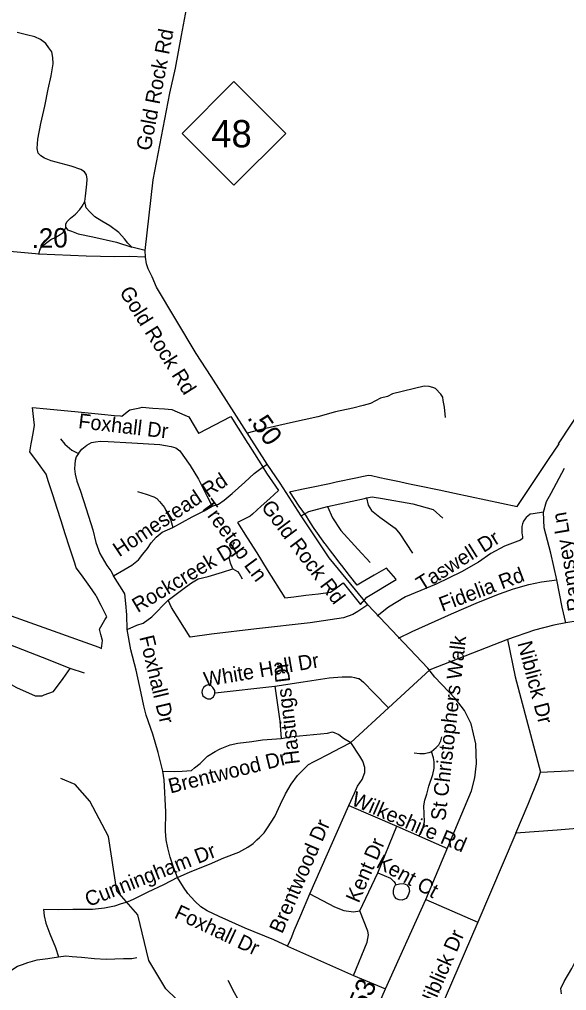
# Model space of a CAD drawing. Extents: x 2220236 to 2384410, y 720751 to 894131.
# Drawn here: x 2350546 to 2354061, y 819071 to 825303 of the extents above; entities that cross this region are included whole.
import ezdxf

# ---------------------------------------------------------------- set-up
doc = ezdxf.new("R2010")
doc.units = 0
doc.layers.add('Default', color=7, linetype='Continuous')

msp = doc.modelspace()

# ---------------------------------------------------------------- linework, layer by layer
at = {"layer": 'Default'}
for p, q in [((2351353.9, 823820.3), (2351267.5, 823841.9)), ((2353681.2, 821325.1), (2353181.5, 821129.2)), ((2350964.3, 821107), (2350872.7, 821138.5)), ((2352916.6, 820884.9), (2353181.5, 821129.2)), ((2351803.3, 820981.7), (2352186.3, 821025.3)), ((2352674.6, 820662.3), (2352916.6, 820884.9)), ((2353892.4, 820473.1), (2354855.4, 820516.7)), ((2352411.4, 819691.4), (2352661.1, 820257.9)), ((2352661.1, 820257.9), (2352969.9, 820125.3)), ((2352848.4, 819825.8), (2352969.9, 820125.3)), ((2352969.9, 820125.3), (2353295.3, 819983.3)), ((2353735.1, 820081.3), (2353490.1, 819510.5)), ((2352733.4, 819583.5), (2352848.4, 819825.8)), ((2353156.4, 819656.6), (2353490.1, 819510.5)), ((2352267.7, 819356), (2352691.2, 819167.9)), ((2352691.2, 819167.9), (2352898.6, 819081.8))]:
    msp.add_line(p, q, dxfattribs=at)
for points in [[(2351355.5, 823776.5), (2351353.9, 823820.3), (2351405, 824274.2), (2351513.6, 824829), (2351549.3, 824991.3), (2351587.4, 825199.7), (2351625.8, 825406.1)], [(2350966.1, 824135.1), (2350971.9, 824170), (2350978.9, 824246.8), (2350982.4, 824278.3), (2350977.1, 824306.2), (2350964.9, 824325.4), (2350940.5, 824341.1), (2350878.6, 824362.1), (2350751.2, 824395.2), (2350707.6, 824412.7), (2350684.9, 824428.4), (2350667.5, 824445.8), (2350660.5, 824475.5), (2350664, 824534.9), (2350683.2, 824636.1), (2350709.3, 824746.1), (2350730.3, 824856.1), (2350749.5, 824941.6), (2350763.4, 825018.5), (2350761.7, 825058.6), (2350754.7, 825095.3), (2350735.5, 825121.5), (2350716.3, 825149.4), (2350681.4, 825173.8), (2350646.5, 825191.3), (2350592.4, 825205.3), (2350533.1, 825219.2)], [(2350844.1, 823968.4), (2350844.1, 823989.3), (2350851.1, 824005), (2350873.8, 824027.7), (2350906.9, 824053.9), (2350934.8, 824083.6), (2350950.5, 824104.6), (2350966.1, 824135.1)], [(2351267.5, 823841.9), (2351242.3, 823868), (2351221.4, 823894.2), (2351184.8, 823936.1), (2351127.2, 823978), (2351074.8, 824007.7), (2351031.2, 824035.6), (2350998.1, 824068.8), (2350975.4, 824094.9), (2350966.1, 824135.1)], [(2350671.4, 823795.5), (2350676.6, 823821.7), (2350681.9, 823834), (2350690.6, 823846.2), (2350722, 823872.4), (2350748.2, 823891.6), (2350781.3, 823905.5), (2350809.2, 823923), (2350826.7, 823935.2), (2350833.6, 823945.7), (2350844.1, 823968.4)], [(2350844.1, 823968.4), (2350856.3, 823952.7), (2350880.8, 823943.9), (2350924.4, 823928.2), (2351018.6, 823909), (2351170.4, 823874.1), (2351267.5, 823841.9)], [(2351355.5, 823776.5), (2351251.8, 823781.3), (2351158.6, 823780.7), (2350975.6, 823783.5), (2350674.4, 823796.4), (2350249.6, 823834.8)], [(2352651.8, 818514.5), (2352898.6, 819081.8), (2353156.4, 819656.6), (2353450.9, 820353.6), (2353471.4, 820436.2), (2353482.4, 820529.3), (2353478.2, 820655.6), (2353448.2, 820783.4), (2353405.1, 820867.6), (2353346.9, 820944.3), (2353214.8, 821083.3), (2353170.1, 821139.6), (2352784.6, 821547.5), (2352535.8, 821847.6), (2352355.3, 822118.1), (2352220.4, 822327), (2352138.6, 822448.7), (2351778.7, 823010.8), (2351681.4, 823158.4), (2351426.1, 823584.2), (2351398.5, 823650.8), (2351373.4, 823701.9), (2351361.8, 823735.5), (2351355.5, 823776.5)], [(2350079.2, 821624.6), (2351057, 821275.5), (2351074, 821267.1), (2351081, 821317.6), (2351070.2, 821356.4), (2351061, 821390.7), (2351096, 821450), (2351107.8, 821470), (2351071.8, 821541.6), (2351042.5, 821599.9), (2351038.2, 821608.3), (2350998.2, 821663.9), (2350944.5, 821738.5), (2350911.5, 821784.3), (2350901.8, 821814.8), (2350869, 821916.4), (2350841.2, 822002.4), (2350814.5, 822085.4), (2350788.8, 822165.6), (2350760.8, 822252.1), (2350734, 822334.9), (2350718, 822384.9), (2350668, 822453.7), (2350614.2, 822528.9), (2350622.8, 822579.4), (2350634.8, 822646), (2350644.2, 822699.1), (2350640, 822735.9), (2350630.8, 822812.1), (2350723, 822803.3), (2350923.5, 822784.2), (2351074.2, 822769.9), (2351156.5, 822762.1), (2351196, 822758.3), (2351204.5, 822757.5), (2351237.8, 822784.2), (2351255, 822798.1), (2351319.8, 822811.1), (2351334.8, 822814.1), (2351404.2, 822809.1), (2351478.8, 822803.8), (2351526.2, 822800.3), (2351608.8, 822763.6), (2351634.2, 822752.1), (2351696.8, 822647.9), (2351698.5, 822648.7), (2351904, 822754.3), (2351950.8, 822680.4), (2352013.5, 822581.4), (2352014.8, 822579.4), (2352082.5, 822475.1), (2352086, 822469.5), (2352133.2, 822391.4), (2352211, 822280.1), (2352155.2, 822229.6), (2352099, 822178.8), (2352043.2, 822128.4), (2352029.5, 822116.1), (2351967.5, 822084.9), (2351948, 822075), (2352009.5, 821977.1), (2352070.5, 821879.9), (2352138.5, 821771.6), (2352251.5, 821591.6), (2352308.2, 821598.5), (2352386.2, 821608.1), (2352468, 821618.1), (2352545, 821627.4), (2352579.8, 821653), (2352582.2, 821655.8), (2352626.8, 821688.4), (2352736.5, 821547.8), (2352777.5, 821594.7), (2352967, 821708.9), (2352964, 821712.6), (2352933.8, 821747.6), (2352903.5, 821782.6), (2352899.8, 821780.3), (2352824.2, 821736.2), (2352748.2, 821691.9), (2352715.2, 821672.7), (2352667, 821734.9), (2352616.5, 821799.5), (2352605, 821814.1), (2352600, 821820.8), (2352579.2, 821847.2), (2352573.5, 821854.8), (2352544.8, 821892.6), (2352512, 821935.8), (2352509, 821939.8), (2352487.5, 821970.3), (2352461.2, 822007.1), (2352440.2, 822036.6), (2352436, 822042.9), (2352404.2, 822090.1), (2352390.2, 822115.1), (2352344.2, 822179.2), (2352283.8, 822271.8), (2352289.2, 822273), (2352369.8, 822290.1), (2352412.5, 822299.2), (2352454, 822308.1), (2352496, 822317.1), (2352538.2, 822326.1), (2352580.2, 822335), (2352622.8, 822344.1), (2352664.2, 822352.9), (2352706.2, 822361.9), (2352755.8, 822372.4), (2352789, 822379.6), (2352808, 822375.6), (2352861.8, 822364.2), (2352902.5, 822355.6), (2352945, 822346.6), (2352986.8, 822337.7), (2353033.2, 822327.8), (2353072.8, 822319.4), (2353115.2, 822310.4), (2353158.2, 822301.4), (2353200.5, 822292.4), (2353242.5, 822283.5), (2353341.2, 822262.6), (2353743.2, 822177.5), (2353944.5, 822478.4), (2353945, 822479.4), (2354012, 822579.4), (2354009.5, 822579.4), (2354356.2, 823104.4)], [(2350079.2, 821624.6), (2351057, 821275.5), (2351074, 821267.1), (2351081, 821317.6), (2351070.2, 821356.4), (2351061, 821390.7), (2351096, 821450), (2351107.8, 821470), (2351071.8, 821541.6), (2351042.5, 821599.9), (2351038.2, 821608.3), (2350998.2, 821663.9), (2350944.5, 821738.5), (2350911.5, 821784.3), (2350901.8, 821814.8), (2350869, 821916.4), (2350841.2, 822002.4), (2350814.5, 822085.4), (2350788.8, 822165.6), (2350760.8, 822252.1), (2350734, 822334.9), (2350718, 822384.9), (2350668, 822453.7), (2350614.2, 822528.9), (2350622.8, 822579.4), (2350634.8, 822646), (2350644.2, 822699.1), (2350640, 822735.9), (2350630.8, 822812.1), (2350723, 822803.3), (2350923.5, 822784.2), (2351074.2, 822769.9), (2351156.5, 822762.1), (2351196, 822758.3), (2351204.5, 822757.5), (2351237.8, 822784.2), (2351255, 822798.1), (2351319.8, 822811.1), (2351334.8, 822814.1), (2351404.2, 822809.1), (2351478.8, 822803.8), (2351526.2, 822800.3), (2351608.8, 822763.6), (2351634.2, 822752.1), (2351696.8, 822647.9), (2351698.5, 822648.7), (2351904, 822754.3), (2351950.8, 822680.4), (2352013.5, 822581.4), (2352014.8, 822579.4), (2352082.5, 822475.1), (2352086, 822469.5), (2352133.2, 822391.4), (2352211, 822280.1), (2352155.2, 822229.6), (2352099, 822178.8), (2352043.2, 822128.4), (2352029.5, 822116.1), (2351967.5, 822084.9), (2351948, 822075), (2352009.5, 821977.1), (2352070.5, 821879.9), (2352138.5, 821771.6), (2352251.5, 821591.6), (2352308.2, 821598.5), (2352386.2, 821608.1), (2352468, 821618.1), (2352545, 821627.4), (2352579.8, 821653), (2352582.2, 821655.8), (2352626.8, 821688.4), (2352736.5, 821547.8), (2352777.5, 821594.7), (2352967, 821708.9), (2352964, 821712.6), (2352933.8, 821747.6), (2352903.5, 821782.6), (2352899.8, 821780.3), (2352824.2, 821736.2), (2352748.2, 821691.9), (2352715.2, 821672.7), (2352667, 821734.9), (2352616.5, 821799.5), (2352605, 821814.1), (2352600, 821820.8), (2352579.2, 821847.2), (2352573.5, 821854.8), (2352544.8, 821892.6), (2352512, 821935.8), (2352509, 821939.8), (2352487.5, 821970.3), (2352461.2, 822007.1), (2352440.2, 822036.6), (2352436, 822042.9), (2352404.2, 822090.1), (2352390.2, 822115.1), (2352344.2, 822179.2), (2352283.8, 822271.8), (2352289.2, 822273), (2352369.8, 822290.1), (2352412.5, 822299.2), (2352454, 822308.1), (2352496, 822317.1), (2352538.2, 822326.1), (2352580.2, 822335), (2352622.8, 822344.1), (2352664.2, 822352.9), (2352706.2, 822361.9), (2352755.8, 822372.4), (2352789, 822379.6), (2352808, 822375.6), (2352861.8, 822364.2), (2352902.5, 822355.6), (2352945, 822346.6), (2352986.8, 822337.7), (2353033.2, 822327.8), (2353072.8, 822319.4), (2353115.2, 822310.4), (2353158.2, 822301.4), (2353200.5, 822292.4), (2353242.5, 822283.5), (2353341.2, 822262.6), (2353743.2, 822177.5), (2353944.5, 822478.4), (2353945, 822479.4), (2354012, 822579.4), (2354009.5, 822579.4), (2354356.2, 823104.4)], [(2353283.2, 822748.9), (2353276.5, 822814.8), (2353267.9, 822858.7), (2353265.7, 822878.6), (2353253.5, 822898.5), (2353219, 822934.1), (2353200.9, 822941.8), (2353178.8, 822947.5), (2353147, 822949.2), (2352943.6, 822900.9), (2352909.7, 822884.3), (2352866, 822871.9), (2352800.3, 822839), (2352753.8, 822825), (2352687.4, 822808.8), (2352577.1, 822784.5), (2352462, 822753.7), (2352286.9, 822714.7), (2352081, 822667.7), (2352009.7, 822648.2)], [(2350809.8, 822612.5), (2350839, 822578.4), (2350882.7, 822539.5), (2350924.9, 822516.7)], [(2350924.9, 822516.7), (2350947.6, 822545.9), (2350980, 822571.9), (2351009.2, 822588.1), (2351035.1, 822593), (2351067.6, 822596.2), (2351116.2, 822594.6), (2351268.6, 822586.5), (2351447.9, 822575.2), (2351520.9, 822563.1), (2351550.1, 822553.3), (2351576.8, 822533.9), (2351596.3, 822507.1), (2351642.5, 822441.4), (2351696, 822353.8), (2351749.5, 822246.7), (2351784.8, 822179.8)], [(2350924.9, 822516.7), (2350911.9, 822495.7), (2350903.8, 822472.9), (2350902.2, 822448.6), (2350900.6, 822419.4), (2350903.8, 822385.4), (2350915.2, 822339.9), (2350937.9, 822276.7), (2350975.2, 822163.1), (2351017.3, 822026.9), (2351036.8, 821947.4), (2351062.7, 821876), (2351108.1, 821798.1), (2351133, 821763.7), (2351150.1, 821732.1)], [(2351784.8, 822179.8), (2351824.9, 822193.2), (2351861.4, 822217.5), (2351912.4, 822261.3), (2351995.1, 822334.3), (2352053.5, 822390.3), (2352097.2, 822421.9), (2352138.6, 822448.7)], [(2353911.4, 822142.1), (2353932.1, 822210.3), (2353962.7, 822263.8), (2354046.8, 822424.5)], [(2351305.7, 822274.7), (2351361.6, 822257.7), (2351410.3, 822240.6), (2351429.7, 822228.5), (2351446.7, 822209), (2351478.3, 822170.1), (2351519.7, 822087.3), (2351531.8, 822043.5)], [(2351531.8, 822043.5), (2351655.9, 822111.7), (2351733.7, 822150.6), (2351784.8, 822179.8)], [(2352355.3, 822118.1), (2352405.1, 822145.3), (2352524.6, 822177.9)], [(2352524.6, 822177.9), (2352762, 822229.6), (2352775.6, 822232.3)], [(2352524.6, 822177.9), (2352557.3, 822105.5), (2352611.6, 822023), (2352719.4, 821903.5), (2352798.2, 821819.2)], [(2352775.6, 822232.3), (2352811.3, 822238.6), (2352878.4, 822228.7), (2353073.1, 822194.2), (2353203.1, 822158), (2353265.6, 822102.7)], [(2352775.6, 822232.3), (2352785.5, 822187), (2352808.2, 822152.6), (2352860.7, 822110), (2352959, 822039.3), (2352990.7, 822003.1), (2353070.4, 821877.2)], [(2353911.4, 822142.1), (2353845.7, 822129.9), (2353826.2, 822127.5), (2353811.7, 822115.3), (2353801.9, 822108), (2353794.6, 822098.3), (2353784.9, 822083.7), (2353777.6, 822066.6), (2353772.7, 822049.6), (2353772.7, 822032.6), (2353772.7, 822008.2), (2353775.2, 821996.1), (2353777.6, 821983.9), (2353777.6, 821971.7), (2353765.4, 821962), (2353660.9, 821923.1), (2353573.3, 821876.8), (2353495.5, 821820.9), (2353386.1, 821757.6), (2353223.2, 821679.7), (2353026.2, 821597), (2352916.8, 821531.3), (2352843.8, 821472.9)], [(2353997.7, 821707.7), (2353958.8, 821878.1), (2353916.2, 822039.9), (2353911.4, 822142.1)], [(2351150.1, 821732.1), (2351218.1, 821771), (2351269.2, 821800.2), (2351310.6, 821834.3), (2351339.7, 821870.8), (2351368.9, 821907.3), (2351393.2, 821943.8), (2351424.8, 821980.3), (2351463.8, 822011.9), (2351531.8, 822043.5)], [(2351917.3, 821777.1), (2351902.7, 821813.6), (2351893, 821850.1)], [(2351238.8, 821387.7), (2351300.8, 821415.2), (2351340.7, 821429.7), (2351397.8, 821469.6), (2351501.5, 821575.5), (2351613.3, 821660.3), (2351652.2, 821687), (2351693.6, 821713.8), (2351759.2, 821728.4), (2351851.6, 821755.2), (2351917.3, 821777.1)], [(2351917.3, 821777.1), (2351946.5, 821760), (2351958.6, 821747.9), (2351978.1, 821713.8)], [(2351238.8, 821387.7), (2351236.4, 821482.6), (2351229.1, 821555.6), (2351224.2, 821616.5), (2351207.2, 821645.7), (2351175.6, 821691.9), (2351150.1, 821732.1)], [(2352982, 821332.1), (2353068.7, 821374.4), (2353321.6, 821488.7), (2353494.3, 821564.2), (2353630.5, 821617.7), (2353720.5, 821649.3), (2353817.7, 821676.1), (2353900.4, 821693.1), (2353997.7, 821707.7)], [(2354054.9, 821431.5), (2354031.7, 821532.5), (2353997.7, 821707.7)], [(2352784.6, 821547.5), (2352719.4, 821503.1), (2352686.8, 821484.1), (2352627, 821463.2), (2352413.2, 821431.5), (2352068.6, 821391.7), (2351780, 821358.1), (2351643.7, 821339.1), (2351524.1, 821530.2), (2351501.5, 821575.5)], [(2354054.9, 821431.5), (2353979.4, 821415.4), (2353853.7, 821383.4), (2353681.2, 821325.1)], [(2354212.4, 821460.8), (2354134.9, 821442.9), (2354054.9, 821431.5)], [(2350872.7, 821138.5), (2350694.6, 821209.4), (2350491.1, 821287.5), (2350291.2, 821369.4)], [(2351467.7, 820478.3), (2351438.6, 820598.1), (2351404.4, 820716.2), (2351361.6, 820837.7), (2351346.2, 820897.6), (2351327.4, 820979.8), (2351296.6, 821127), (2351263.1, 821258.8), (2351238.8, 821387.7)], [(2353681.2, 821325.1), (2353731, 821085), (2353892.4, 820473.1)], [(2350219.5, 821151.6), (2350392.9, 821091.2), (2350527.4, 821016.6), (2350647.9, 820963.2), (2350693.2, 820963), (2350706.3, 820968.3), (2350765.5, 820989.4), (2350827.3, 821074.8), (2350872.7, 821138.5)], [(2352186.3, 821025.3), (2352369.1, 821053), (2352536, 821078.1), (2352618.3, 821085), (2352661.8, 821085.3), (2352678.6, 821084.2), (2352698.3, 821081), (2352721.5, 821073.7), (2352728, 821073.8), (2352757.4, 821049.6), (2352823.7, 820981.2), (2352916.6, 820884.9)], [(2351800.7, 820997.8), (2351788.6, 821015.5), (2351776.4, 821029.4), (2351758.2, 821033.3), (2351746.4, 821029), (2351728.5, 821016.8), (2351720.8, 820998.7), (2351719, 820984.8), (2351725.1, 820962.9), (2351745.3, 820947.1), (2351755.3, 820943.1), (2351773.3, 820943.4), (2351793.2, 820955.7), (2351801, 820975.8), (2351800.7, 820997.8)], [(2352186.3, 821025.3), (2352218.3, 820799.1), (2352227.4, 820689.4)], [(2351467.7, 820478.3), (2351541.7, 820476.7), (2351592, 820479), (2351651.4, 820483.6), (2351672, 820499.6), (2351706.3, 820529.3), (2351754.3, 820575), (2351804.6, 820604.8), (2351836.6, 820623.1), (2351900.6, 820648.2), (2351949.5, 820659), (2352038.6, 820669.2), (2352108.6, 820680.2), (2352227.4, 820689.4)], [(2352227.4, 820689.4), (2352300.6, 820700.8), (2352481.1, 820719.1), (2352524.6, 820723.7), (2352557.7, 820731), (2352597.8, 820713.4), (2352628.1, 820691.8), (2352674.6, 820662.3)], [(2353192.2, 820604.5), (2353223, 820631.9), (2353240.1, 820649), (2353253.8, 820673), (2353258.9, 820700.4)], [(2351561.9, 819796), (2351642.6, 819832.6), (2351767.4, 819882.3), (2351859.8, 819923.3), (2351955.6, 819959.3), (2352013.7, 819991.8), (2352047.9, 820015.8), (2352071.9, 820038), (2352089, 820053.4), (2352118.1, 820082.5), (2352140.3, 820115), (2352186.5, 820188.6), (2352222.4, 820267.4), (2352254.9, 820334.1), (2352290.8, 820395.7), (2352331.9, 820450.5), (2352372.9, 820491.6), (2352403.7, 820522.4), (2352434.5, 820539.5), (2352461, 820552.3), (2352526.9, 820585.7), (2352612.4, 820631.2), (2352674.6, 820662.3)], [(2352661.1, 820257.9), (2352699.6, 820337.5), (2352718.4, 820382), (2352748.6, 820426.4), (2352764, 820470.7), (2352765.7, 820502.6), (2352753.1, 820543), (2352732.6, 820575), (2352674.6, 820662.3)], [(2353082.7, 820596), (2353118.7, 820592.5), (2353147.7, 820592.5), (2353164.8, 820596), (2353177.8, 820600), (2353184.8, 820601.7), (2353192.2, 820604.5)], [(2353113.5, 820063.7), (2353139.2, 820121.9), (2353147.7, 820154.4), (2353146, 820205.7), (2353144.3, 820257.1), (2353151.2, 820293), (2353163.1, 820332.4), (2353176.8, 820383.7), (2353202.5, 820457.3), (2353209.3, 820498.4), (2353209.3, 820539.5), (2353205.9, 820565.2), (2353192.2, 820604.5)], [(2351689.5, 818886.2), (2351487.5, 819081.4), (2351376.6, 819264), (2351306.7, 819556.5), (2351171.5, 819711.9), (2351117.6, 820060.8), (2350998.5, 820285.7), (2350905.6, 820393.5), (2350813.5, 820432.4)], [(2351561.9, 819796), (2351536.7, 819863.8), (2351514.6, 819927), (2351500.4, 819986.9), (2351489.4, 820039), (2351484.6, 820094.3), (2351487.8, 820217.4), (2351476.2, 820423.5), (2351467.7, 820478.3)], [(2353735.1, 820081.3), (2353814.7, 820268.3), (2353880.8, 820432.8), (2353892.4, 820473.1)], [(2354868.1, 820129), (2354386.3, 820123.1), (2354232.4, 820119.3), (2354000.9, 820100.4), (2353735.1, 820081.3)], [(2352848.4, 819825.8), (2352928.8, 819791.7), (2352951, 819772), (2352959.3, 819760.2), (2352961.3, 819750)], [(2351561.9, 819796), (2351471.5, 819750.5), (2351372.3, 819702.6), (2351281.7, 819658.1), (2351238.9, 819637.5), (2351199.6, 819627.3), (2351156.8, 819613.6), (2351093.5, 819599.9), (2351014.8, 819591.3), (2350890, 819591.3), (2350797.6, 819589.6), (2350701.8, 819591.3), (2350705.2, 819550.2), (2350715.5, 819504), (2350742.9, 819435.6), (2350778.8, 819346.6), (2350797.6, 819286.7)], [(2352267.7, 819356), (2352180.2, 819396.7), (2351997.2, 819472.5), (2351830, 819546.6), (2351752.8, 819582.9), (2351711.7, 819608.2), (2351673.9, 819644.5), (2351628.2, 819695), (2351601.3, 819734.4), (2351561.9, 819796)], [(2352961.3, 819750), (2352987.2, 819756.5), (2353013.2, 819758.7), (2353035.4, 819749.1), (2353047.4, 819733.1), (2353051.8, 819709.3), (2353044.1, 819683.2), (2353030.4, 819661), (2353004.6, 819650.8), (2352986.4, 819654.4), (2352968.4, 819660.3), (2352956.2, 819674), (2352948.1, 819692.1), (2352949.8, 819713.9), (2352953.6, 819732.1), (2352961.3, 819750)], [(2352267.7, 819356), (2352288.2, 819397.1), (2352295.1, 819415.9), (2352303.6, 819439.8), (2352311, 819456.4), (2352353.8, 819555), (2352411.4, 819691.4)], [(2352411.4, 819691.4), (2352571.1, 819609.4), (2352629.5, 819584.2), (2352691.4, 819576.9), (2352733.4, 819583.5)], [(2352691.2, 819167.9), (2352779.5, 819380.9), (2352787.4, 819428.3), (2352784.2, 819451.9), (2352733.4, 819583.5)], [(2353490.1, 819510.5), (2353279.9, 819024.1), (2353225.3, 818909.7), (2353190.4, 818829.2), (2353161.3, 818752.8), (2353144.1, 818678.6), (2353136.9, 818614.5), (2353140.3, 818502.6)], [(2354027.5, 819051.3), (2354022.9, 819085.1), (2354044.5, 819129.4), (2354093.5, 819213.8), (2354146.1, 819316.6), (2354187.4, 819376.9), (2354242.6, 819437.6), (2354288.1, 819480.1), (2354347.8, 819512.9), (2354413.3, 819539.6), (2354475.3, 819550.3), (2354563.2, 819553.5), (2354723.3, 819533.5), (2354821.7, 819510.7)], [(2350296.5, 819052.2), (2350330.7, 819077.9), (2350387.1, 819124.1), (2350448.7, 819172), (2350498.3, 819204.5), (2350534.2, 819226.8), (2350566.7, 819238.7), (2350600.9, 819252.4), (2350660.8, 819267.8), (2350729.2, 819278.1), (2350797.6, 819286.7)], [(2350797.6, 819286.7), (2350843.8, 819293.5), (2350884.8, 819290.1), (2350944.7, 819284.9), (2351028.5, 819276.4), (2351103.8, 819273), (2351215, 819276.4), (2351268, 819278.1), (2351300.5, 819283.2)], [(2351886, 819138.7), (2351925.5, 819059.8), (2351983.8, 818957.2), (2352015.4, 818897.2), (2352043.7, 818849.9), (2352073.7, 818807.2), (2352094.2, 818782), (2352127.3, 818752), (2352160.5, 818731.5), (2352206.2, 818699.9), (2352283.5, 818660.5), (2352373.4, 818621), (2352486.9, 818576.8)]]:
    msp.add_lwpolyline(points, dxfattribs=at)
msp.add_lwpolyline([(2351591.4, 824572), (2351924.4, 824905), (2352257.3, 824572), (2351924.4, 824239)], close=True, dxfattribs=at)

# ---------------------------------------------------------------- texts
for s, height, rotation, p in [('Gold Rock Rd', 95, 79.17506, (2351388.8, 824455.9)), ('.20', 125, 0.76229, (2350625.4, 823836.8)), ('Gold Rock Rd', 95, 302.23534, (2351185.2, 823553.9)), ('Foxhall Dr', 95, 353.25128, (2350921.3, 822681.4)), ('.50', 125, 305.42332, (2352006, 822746.3)), ('Homestead Rd', 95, 33.70341, (2351187.4, 821850.7)), ('Treetop Ln', 95, 306.48756, (2351703.5, 822180.2)), ('Gold Rock Rd', 95, 306.90304, (2352094.7, 822173.9)), ('Ramsey Ln', 95, 99.65508, (2354164.8, 821514.8)), ('Taswell Dr', 95, 32.07818, (2353132.4, 821631.1)), ('Rockcreek Dr', 95, 30.88966, (2351306.1, 821493.5)), ('Fidelia Rd', 95, 20.59329, (2353262.7, 821500.7)), ('Foxhall Dr', 95, 283.50705, (2351316.2, 821339.3)), ('St Christophers Walk', 95, 83.52007, (2353281.8, 820158)), ('Niblick Dr', 95, 284.75331, (2353744.5, 821300.5)), ('White Hall Dr', 95, 9.73239, (2351738.8, 821019.8)), ('Hastings Dr', 95, 96.78565, (2352348.9, 820527.6)), ('Brentwood Dr', 95, 13.97356, (2351516, 820335.3)), ('Wilkeshire Rd', 95, 336.79082, (2352671.6, 820264.7)), ('Brentwood Dr', 95, 66.44661, (2352233.9, 819431.4)), ('Cunningham Dr', 95, 21.42696, (2350989.8, 819607.2)), ('Kent Dr', 95, 66.67666, (2352725.5, 819627.9)), ('Kent Ct', 95, 331.24788, (2352831.5, 819865.6)), ('Foxhall Dr', 95, 334.79815, (2351535.1, 819540.6)), ('Niblick Dr', 95, 66.63787, (2353191.5, 818936.1)), ('1.53', 125, 66.48848, (2352713.5, 818813))]:
    msp.add_text(s, height=height, rotation=rotation, dxfattribs=at).set_placement(p)
msp.add_text('48', height=175, dxfattribs=at).set_placement((2351778.5, 824482.3))

doc.saveas('drawing.dxf')
